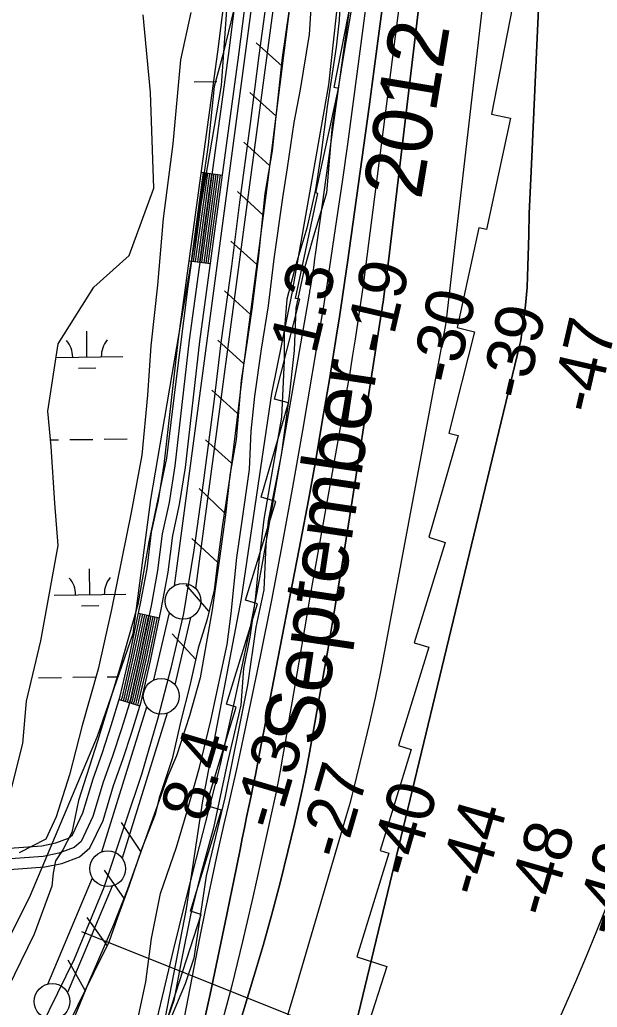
# Model space of a CAD drawing. Extents: x 3715084 to 3753216, y 488173 to 513963.
# Drawn here: x 3732143 to 3732951, y 502700 to 504083 of the extents above; entities that cross this region are included whole.
import ezdxf

# ---------------------------------------------------------------- set-up
doc = ezdxf.new("R2010")
doc.units = 0
for name, color, linetype in [('V-FLOD-BASE', 7, 'Continuous'), ('V-LEVE-TOET', 7, 'Continuous'), ('V-RIVR-EDGE', 7, 'Continuous'), ('V-RIVR-IDEN', 7, 'Continuous'), ('V-RIVR-RANG', 7, 'Continuous'), ('V-ROAD-CNTR', 7, 'Continuous'), ('V-RRAP-FSHR', 7, 'Continuous'), ('V-RRAP-RVMT', 7, 'Continuous'), ('V-SITE-VEGE', 7, 'Continuous'), ('V-SURV-LINE', 7, 'Continuous'), ('V-TOPO-DPTH', 7, 'Continuous'), ('V-TOPO-MAJR', 7, 'Continuous'), ('V-TOPO-MINR', 7, 'Continuous'), ('V-TOPO-WATR', 7, 'Continuous'), ('V-WETL-SWMP', 7, 'Continuous')]:
    doc.layers.add(name, color=color, linetype=linetype)

msp = doc.modelspace()

# ---------------------------------------------------------------- linework, layer by layer
at = {"layer": 'V-FLOD-BASE'}
msp.add_lwpolyline([(3732486.7, 504101), (3732477.1, 504032.8), (3732465.1, 503937.3), (3732449.9, 503823.6), (3732439.1, 503737.6), (3732424.5, 503634), (3732413.8, 503544.2), (3732399.2, 503434.3), (3732386.5, 503340.1), (3732371.9, 503251.6), (3732354.2, 503175.1), (3732335.9, 503105), (3732313.1, 503026), (3732290.9, 502959.6), (3732260.6, 502868), (3732218.8, 502767.5), (3732148.6, 502624.1)], dxfattribs=at)
at = {"layer": 'V-LEVE-TOET'}
for points in [[(3732456.3, 504155.4), (3732427.2, 504035.3), (3732414.6, 503989.2), (3732406.3, 503907.6), (3732391.1, 503800.8), (3732377.8, 503709.2), (3732360, 503568.9), (3732348, 503469), (3732323.3, 503352.1), (3732308.1, 503264.3), (3732282.8, 503175.2), (3732251.8, 503072.8), (3732225.2, 502990), (3732215.7, 502945.1), (3732203.1, 502920.5), (3732192.9, 502905.3), (3732189.8, 502888.2), (3732187.9, 502869.9), (3732163.2, 502802.9), (3732117, 502708.1), (3732083.5, 502637.4)], [(3732519.2, 504094.3), (3732509.7, 504029.8), (3732503.4, 503969.1), (3732495.7, 503899), (3732485.6, 503839.6), (3732476.7, 503752.4), (3732467.9, 503681), (3732460.9, 503632.9), (3732452.7, 503577.9), (3732445.7, 503495.1), (3732436.8, 503445.2), (3732430.5, 503389.6), (3732421.6, 503325.1), (3732412.1, 503256.9), (3732395, 503161.4), (3732380.4, 503108.4), (3732362.1, 503052.1), (3732350.1, 503023.7), (3732322.2, 502945.3), (3732293.1, 502864.4), (3732274.1, 502815.8), (3732239.3, 502736.1), (3732207.7, 502658.4)]]:
    msp.add_lwpolyline(points, dxfattribs=at)
at = {"layer": 'V-RIVR-EDGE'}
msp.add_lwpolyline([(3732610.8, 504121.1), (3732594.9, 504027.5), (3732579.7, 503934.5), (3732571.7, 503840.3), (3732552.9, 503776.7), (3732540.8, 503733.5), (3732529.2, 503678.9), (3732526.7, 503619.5), (3732519.9, 503556.4), (3732508.3, 503473), (3732490.1, 503381.2), (3732487, 503347.6), (3732484.4, 503284.6), (3732472.9, 503232.4), (3732461.3, 503151.4), (3732449.2, 503090.8), (3732429.7, 502993.6), (3732403.6, 502884.4), (3732386.5, 502769.1), (3732374.4, 502733.2), (3732353.9, 502684)], dxfattribs=at)
at = {"layer": 'V-RIVR-RANG'}
msp.add_line((3732229.3, 502806.2), (3732823.6, 502568.7), dxfattribs=at)
at = {"layer": 'V-ROAD-CNTR'}
for p, q in [((3732396.8, 503869.2), (3732426.5, 503865.1)), ((3732379.9, 503745.3), (3732409.6, 503741.3)), ((3732308.9, 503251.8), (3732338.3, 503245.6)), ((3732282.1, 503131.1), (3732310.7, 503122.3))]:
    msp.add_line(p, q, dxfattribs=at)
for points in [[(3731140.1, 502909.1), (3731460.2, 502909.4), (3731837.7, 502913.8), (3732083.1, 502919.7), (3732173.7, 502926.4), (3732193.3, 502930.5), (3732211.1, 502937.1), (3732216.7, 502941.9), (3732231.2, 502972.7), (3732245.4, 503020.3), (3732258.6, 503056.9), (3732270.9, 503094.6), (3732283.5, 503135.8), (3732296.3, 503191.6), (3732311.8, 503265.4), (3732320.9, 503314.1), (3732327.1, 503365.6), (3732337, 503409.7), (3732344.9, 503460.2), (3732365, 503636.2), (3732419.7, 504037.6), (3732449.2, 504271.2)], [(3732464.1, 504269.6), (3732434.6, 504035.7), (3732379.9, 503634.4), (3732359.8, 503458.2), (3732351.7, 503406.9), (3732341.9, 503363.1), (3732335.7, 503311.8), (3732326.5, 503262.5), (3732310.9, 503188.4), (3732298, 503131.9), (3732285.2, 503090), (3732272.8, 503052), (3732259.7, 503015.6), (3732245.3, 502967.3), (3732228.9, 502932.6), (3732218.9, 502924), (3732197.4, 502916.1), (3732175.8, 502911.6), (3732083.8, 502904.7), (3731837.9, 502898.8), (3731460.3, 502894.4), (3731140.2, 502894.1)], [(3731140.2, 502879.1), (3731460.4, 502879.4), (3731838.2, 502883.8), (3732084.6, 502889.8), (3732177.9, 502896.7), (3732201.6, 502901.6), (3732226.6, 502910.8), (3732241.1, 502923.3), (3732259.3, 502961.9), (3732274, 503011), (3732287, 503047.2), (3732299.5, 503085.5), (3732312.5, 503128), (3732325.6, 503185.2), (3732341.2, 503259.5), (3732350.6, 503309.5), (3732356.8, 503360.6), (3732366.5, 503404.1), (3732374.6, 503456.1), (3732394.8, 503632.5), (3732449.5, 504033.7), (3732479, 504268)], [(3732382.9, 503744.9), (3732399.7, 503868.8)], [(3732385.8, 503744.5), (3732402.7, 503868.4)], [(3732388.8, 503744.1), (3732405.7, 503868)], [(3732391.8, 503743.7), (3732408.7, 503867.6)], [(3732394.7, 503743.3), (3732411.6, 503867.2)], [(3732397.7, 503742.9), (3732414.6, 503866.8)], [(3732400.7, 503742.5), (3732417.6, 503866.4)], [(3732403.7, 503742.1), (3732420.5, 503866)], [(3732406.6, 503741.7), (3732423.5, 503865.5)], [(3732284.9, 503130.2), (3732286.4, 503135), (3732299.2, 503191), (3732311.9, 503251.2)], [(3732287.8, 503129.4), (3732289.3, 503134.3), (3732302.1, 503190.3), (3732314.8, 503250.6)], [(3732290.7, 503128.5), (3732292.2, 503133.5), (3732305.1, 503189.7), (3732317.7, 503249.9)], [(3732293.5, 503127.6), (3732295.1, 503132.7), (3732308, 503189), (3732320.7, 503249.3)], [(3732296.4, 503126.7), (3732298, 503131.9), (3732310.9, 503188.4), (3732323.6, 503248.7)], [(3732299.3, 503125.8), (3732300.9, 503131.2), (3732313.9, 503187.7), (3732326.5, 503248.1)], [(3732302.1, 503125), (3732303.8, 503130.4), (3732316.8, 503187.1), (3732329.5, 503247.5)], [(3732305, 503124.1), (3732306.7, 503129.6), (3732319.7, 503186.5), (3732332.4, 503246.9)], [(3732307.9, 503123.2), (3732309.6, 503128.8), (3732322.7, 503185.8), (3732335.4, 503246.2)]]:
    msp.add_lwpolyline(points, dxfattribs=at)
at = {"layer": 'V-RRAP-FSHR'}
for p, q in [((3732509.9, 504017.6), (3732473.7, 504050.4)), ((3732501.1, 503948.2), (3732464.9, 503981)), ((3732492.3, 503878.7), (3732456.1, 503911.5)), ((3732483.3, 503809.3), (3732447.3, 503842.2)), ((3732474.3, 503739.9), (3732438.2, 503772.8)), ((3732465.2, 503670.5), (3732429.2, 503703.4)), ((3732456.2, 503601.1), (3732420.1, 503634)), ((3732447.6, 503531.6), (3732411.3, 503564.3)), ((3732439, 503462.1), (3732402.7, 503494.8)), ((3732428.9, 503392.9), (3732393.6, 503426.6)), ((3732419.3, 503323.5), (3732383.4, 503356.6)), ((3732407.5, 503254.7), (3732375.5, 503291.5)), ((3732389, 503187.2), (3732356.1, 503223.3)), ((3732312.2, 502918.4), (3732285.1, 502959)), ((3732289.3, 502852.3), (3732261.5, 502892.4)), ((3732265.8, 502786.3), (3732237.2, 502825.9)), ((3732234.2, 502723.9), (3732210.4, 502766.5))]:
    msp.add_line(p, q, dxfattribs=at)
for points in [[(3732657, 504737.7), (3732623.4, 504423.9), (3732606.3, 504281.7), (3732574.5, 503991.8), (3732523.5, 503699.8), (3732494.9, 503559.3), (3732452.7, 503272.7), (3732398.5, 502989.1), (3732375.8, 502838.2), (3732346.1, 502686.7), (3732360.7, 502650.7)], [(3732534.3, 504210.7), (3732488.4, 503847.8), (3732455.4, 503595.5), (3732437, 503446.3), (3732426.3, 503376.2), (3732419.7, 503326.5), (3732414.9, 503284.3), (3732404.8, 503243.6), (3732392.5, 503203), (3732380.8, 503150.6), (3732368.2, 503101.4), (3732355.9, 503048.3), (3732337.8, 502993.6), (3732332.3, 502970.2), (3732313.8, 502922.5), (3732295.5, 502869.2), (3732279.5, 502825.9), (3732267.5, 502791.3), (3732245.8, 502747.9), (3732223.7, 502702.3), (3732204.2, 502662.3)], [(3732531.1, 504185), (3732488.4, 503847.8), (3732455.4, 503595.5), (3732437, 503446.3), (3732426.3, 503376.2), (3732419.7, 503326.5), (3732414.9, 503284.3), (3732404.8, 503243.6), (3732392.5, 503203), (3732382.2, 503156.7)], [(3732327.8, 502958.4), (3732313.8, 502922.5), (3732295.5, 502869.2), (3732279.5, 502825.9), (3732267.5, 502791.3), (3732245.8, 502747.9), (3732223.7, 502702.3), (3732223.6, 502702)]]:
    msp.add_lwpolyline(points, dxfattribs=at)
at = {"layer": 'V-RRAP-RVMT'}
for p, q in [((3732582.5, 503987.7), (3732609.8, 504126.9)), ((3732832.3, 504101.1), (3732802.6, 503950.7)), ((3732557.1, 503840.2), (3732588.5, 503986.5)), ((3732588.5, 503986.5), (3732582.5, 503987.7)), ((3732829.4, 503945), (3732795.9, 503789)), ((3732802.6, 503950.7), (3732829.4, 503945)), ((3732528.5, 503692.7), (3732560, 503839.6)), ((3732560, 503839.6), (3732557.1, 503840.2)), ((3732784.9, 503791.3), (3732754.8, 503651.9)), ((3732795.9, 503789), (3732784.9, 503791.3)), ((3732499.2, 503551.6), (3732534.4, 503691.4)), ((3732534.4, 503691.4), (3732528.5, 503692.7)), ((3732778.8, 503645.8), (3732743.2, 503504.2)), ((3732754.8, 503651.9), (3732778.8, 503645.8)), ((3732480.7, 503414.4), (3732518.9, 503546.6)), ((3732518.9, 503546.6), (3732499.2, 503551.6)), ((3732743.2, 503504.2), (3732756, 503500.6)), ((3732756, 503500.6), (3732714.9, 503358.2)), ((3732458.5, 503270.1), (3732501, 503408.5)), ((3732501, 503408.5), (3732480.7, 503414.4)), ((3732737.7, 503351), (3732694.5, 503210.7)), ((3732714.9, 503358.2), (3732737.7, 503351)), ((3732475.3, 503264.9), (3732458.5, 503270.1)), ((3732432.2, 503124.8), (3732475.3, 503264.9)), ((3732715, 503204.3), (3732672.7, 503066.6)), ((3732694.5, 503210.7), (3732715, 503204.3)), ((3732403.4, 502983), (3732445.7, 503120.6)), ((3732445.7, 503120.6), (3732432.2, 503124.8)), ((3732690.4, 503061.2), (3732646.9, 502919.8)), ((3732672.7, 503066.6), (3732690.4, 503061.2)), ((3732425.2, 502976.1), (3732403.4, 502983)), ((3732381.7, 502834.8), (3732425.2, 502976.1)), ((3732659.1, 502916), (3732614.4, 502771.1)), ((3732646.9, 502919.8), (3732659.1, 502916)), ((3732350.9, 502689), (3732396.6, 502830.3)), ((3732396.6, 502830.3), (3732381.7, 502834.8)), ((3732614.4, 502771.1), (3732656.4, 502757.6)), ((3732656.4, 502757.6), (3732607.4, 502606.1))]:
    msp.add_line(p, q, dxfattribs=at)
at = {"layer": 'V-SITE-VEGE'}
for points in [[(3732308.9, 502687.9), (3732319, 502736), (3732327.2, 502796.6), (3732339.9, 502859.8), (3732362, 502924.3), (3732377.2, 502974.9), (3732394.3, 503036.2), (3732410.1, 503101.9), (3732432.9, 503208.1), (3732438.6, 503251.7), (3732446.3, 503330.1), (3732454.5, 503384.4), (3732464, 503453.3), (3732466.5, 503507), (3732471.6, 503555.7), (3732481.1, 503621.4), (3732490.6, 503682.1), (3732498.9, 503747.9), (3732510.9, 503833.2), (3732517.2, 503875.5), (3732526.7, 503938.7), (3732535.6, 503984.9), (3732548.3, 504062), (3732552.1, 504129)], [(3732591.9, 504130.9), (3732589.4, 504082.2), (3732585.6, 504044.3), (3732572.9, 503961.5), (3732564, 503893.2), (3732556.4, 503845.2), (3732544.4, 503790.8), (3732529.2, 503739.6), (3732516.5, 503691.6), (3732512.7, 503644.8), (3732512.7, 503605.6), (3732508.9, 503526.6), (3732484.2, 503383.8), (3732477.2, 503323.7), (3732472.1, 503271.3), (3732464.5, 503218.2), (3732455.7, 503174.6), (3732451.9, 503123.4), (3732432.9, 503041.8), (3732413.9, 502951.5), (3732395.5, 502885.1), (3732382.2, 502831.4), (3732368.9, 502766.9), (3732358.2, 502710), (3732342.3, 502663.9)], [(3732382.2, 504092.8), (3732367.6, 504026.4), (3732356.8, 503908.9), (3732343.5, 503804.6), (3732335.3, 503711), (3732326.4, 503626.3), (3732321.3, 503557.4), (3732313.7, 503473.4), (3732298.5, 503393.1), (3732285.8, 503328.6), (3732271.3, 503257.2), (3732252.3, 503173.8), (3732230.1, 503094.8), (3732212.4, 503025.9), (3732194, 502967.1), (3732179.5, 502935.5), (3732142.2, 502916.6)]]:
    msp.add_lwpolyline(points, dxfattribs=at)
at = {"layer": 'V-SURV-LINE'}
for points in [[(3732359.1, 503290.5), (3732526.7, 504546.7)], [(3732556.5, 504542.7), (3732388.8, 503286.5)], [(3732330.5, 503158.6), (3732352.2, 503252.6)], [(3732381.5, 503245.9), (3732359.8, 503151.9)], [(3732257.5, 502917.8), (3732320.4, 503121.1)], [(3732349.1, 503112.2), (3732286.2, 502908.9)], [(3732182, 502732.8), (3732244.4, 502881.6)], [(3732272, 502870), (3732209.7, 502721.2)]]:
    msp.add_lwpolyline(points, dxfattribs=at)
for centre in [(3732371.3, 503268.7), (3732340.7, 503135.7), (3732265.9, 502894.3), (3732188.1, 502708.6)]:
    msp.add_circle(centre, 25, dxfattribs=at)
at = {"layer": 'V-TOPO-DPTH'}
for points in [[(3732626.4, 504261.1), (3732556.6, 503757.3), (3732555.3, 503748.2), (3732554, 503739.1), (3732552.6, 503730), (3732551.2, 503720.9), (3732548.9, 503706.9), (3732548.6, 503704.9), (3732548.3, 503702.8), (3732547.9, 503700.7), (3732547.5, 503698.6), (3732483.1, 503329.6), (3732474.3, 503281.1), (3732465, 503232.7), (3732455.1, 503184.5), (3732444.7, 503136.3), (3732429.9, 503069.7), (3732426.5, 503054.9), (3732423, 503040.2), (3732419.4, 503025.4), (3732415.7, 503010.7), (3732389.6, 502909.2), (3732373.3, 502844.8), (3732357.3, 502780.2), (3732341.9, 502715.5), (3732326.7, 502650.8)], [(3732719.2, 504255), (3732662, 503772.2), (3732660.1, 503756.6), (3732658.2, 503741.1), (3732656.2, 503725.6), (3732654.1, 503710.1), (3732651, 503687.5), (3732650.4, 503683.3), (3732649.8, 503679.1), (3732649.1, 503674.9), (3732648.5, 503670.7), (3732605.5, 503394.3), (3732595.2, 503329.5), (3732584.6, 503264.8), (3732573.6, 503200.1), (3732562.2, 503135.5), (3732548, 503056.4), (3732543.3, 503031.4), (3732538.3, 503006.5), (3732532.9, 502981.6), (3732527.1, 502956.8), (3732517.9, 502918.3), (3732506.9, 502874.4), (3732495.4, 502830.6), (3732483.2, 502787), (3732470.5, 502743.6), (3732406.1, 502530.1)], [(3732406.1, 502530.1), (3732470.5, 502743.6), (3732483.2, 502787), (3732495.4, 502830.6), (3732506.9, 502874.4), (3732517.9, 502918.3), (3732527.1, 502956.8), (3732532.9, 502981.6), (3732538.3, 503006.5), (3732543.3, 503031.4), (3732548, 503056.4), (3732562.2, 503135.5), (3732573.6, 503200.1), (3732584.6, 503264.8), (3732595.2, 503329.5), (3732605.5, 503394.3), (3732648.5, 503670.7), (3732649.1, 503674.9), (3732649.8, 503679.1), (3732650.4, 503683.3), (3732651, 503687.5), (3732654.1, 503710.1), (3732656.2, 503725.6), (3732658.2, 503741.1), (3732660.1, 503756.6), (3732662, 503772.2), (3732719.2, 504255)], [(3732807.4, 504254.4), (3732738.9, 503658.3), (3732654.6, 503206.9), (3732647.4, 503170), (3732639.8, 503133.3), (3732631.6, 503096.6), (3732622.9, 503060), (3732609.8, 503006.2), (3732607.4, 502996.6), (3732604.9, 502987.1), (3732602.2, 502977.6), (3732599.5, 502968.1), (3732527.6, 502723.5), (3732514, 502678.3)], [(3732807.4, 504254.4), (3732738.9, 503658.3), (3732654.6, 503206.9), (3732647.4, 503170), (3732639.8, 503133.3), (3732631.6, 503096.6), (3732622.9, 503060), (3732609.8, 503006.2), (3732607.4, 502996.6), (3732604.9, 502987.1), (3732602.2, 502977.6), (3732599.5, 502968.1), (3732527.6, 502723.5), (3732514, 502678.3)], [(3732401, 502681.1), (3732409.3, 502718.5), (3732432.5, 502830.2), (3732437.2, 502852.9), (3732441.8, 502875.6), (3732446.4, 502898.3), (3732451, 502921), (3732454.1, 502936.7), (3732457.1, 502951.6), (3732460.1, 502966.4), (3732463.2, 502981.2), (3732466.4, 502996.1), (3732469.5, 503010.9), (3732472.5, 503025.7), (3732475.5, 503040.6), (3732478.4, 503055.4), (3732536, 503354.2), (3732546.6, 503410.4), (3732556.8, 503466.6), (3732566.5, 503522.9), (3732575.9, 503579.2), (3732586, 503641.2), (3732590.1, 503666.7), (3732594, 503692.1), (3732597.7, 503717.5), (3732601.3, 503743), (3732631.5, 503961), (3732638.7, 504013.9), (3732645.8, 504066.9), (3732652.8, 504119.9)], [(3732401, 502681.1), (3732409.3, 502718.5), (3732432.5, 502830.2), (3732437.2, 502852.9), (3732441.8, 502875.6), (3732446.4, 502898.3), (3732451, 502921), (3732454.1, 502936.7), (3732457.1, 502951.6), (3732460.1, 502966.4), (3732463.2, 502981.2), (3732466.4, 502996.1), (3732469.5, 503010.9), (3732472.5, 503025.7), (3732475.5, 503040.6), (3732478.4, 503055.4), (3732536, 503354.2), (3732546.6, 503410.4), (3732556.8, 503466.6), (3732566.5, 503522.9), (3732575.9, 503579.2), (3732586, 503641.2), (3732590.1, 503666.7), (3732594, 503692.1), (3732597.7, 503717.5), (3732601.3, 503743), (3732631.5, 503961), (3732638.7, 504013.9), (3732645.8, 504066.9), (3732652.8, 504119.9)], [(3732616, 502689.8), (3732682.2, 502964.6), (3732842, 503626.4), (3732842.8, 503630.1), (3732843.6, 503633.8), (3732844.2, 503637.6), (3732844.8, 503641.4), (3732848, 503663.5), (3732849.9, 503678.3), (3732851.4, 503693.2), (3732852.4, 503708.2), (3732853.1, 503723.1), (3732853.8, 503752.3), (3732854.7, 503781.8), (3732855.6, 503811.4), (3732856.7, 503840.9), (3732858, 503870.4), (3732866.9, 504067.5), (3732868.3, 504097.8)], [(3732616, 502689.8), (3732682.2, 502964.6), (3732842, 503626.4), (3732842.8, 503630.1), (3732843.6, 503633.8), (3732844.2, 503637.6), (3732844.8, 503641.4), (3732848, 503663.5), (3732849.9, 503678.3), (3732851.4, 503693.2), (3732852.4, 503708.2), (3732853.1, 503723.1), (3732853.8, 503752.3), (3732854.7, 503781.8), (3732855.6, 503811.4), (3732856.7, 503840.9), (3732858, 503870.4), (3732866.9, 504067.5), (3732868.3, 504097.8)]]:
    msp.add_lwpolyline(points, dxfattribs=at)
at = {"layer": 'V-TOPO-MAJR'}
msp.add_lwpolyline([(3732975.1, 502870.4), (3732949.7, 502806.9), (3732935.2, 502771.4), (3732920.4, 502736), (3732905, 502700.9), (3732889.4, 502665.8)], dxfattribs=at)
at = {"layer": 'V-TOPO-MINR'}
for points in [[(3732719.2, 504255), (3732662, 503772.2), (3732660.1, 503756.6), (3732658.2, 503741.1), (3732656.2, 503725.6), (3732654.1, 503710.1), (3732651, 503687.5), (3732650.4, 503683.3), (3732649.8, 503679.1), (3732649.1, 503674.9), (3732648.5, 503670.7), (3732605.5, 503394.3), (3732595.2, 503329.5), (3732584.6, 503264.8), (3732573.6, 503200.1), (3732562.2, 503135.5), (3732548, 503056.4), (3732543.3, 503031.4), (3732538.3, 503006.5), (3732532.9, 502981.6), (3732527.1, 502956.8), (3732517.9, 502918.3), (3732506.9, 502874.4), (3732495.4, 502830.6), (3732483.2, 502787), (3732470.5, 502743.6), (3732406.1, 502530.1)], [(3732807.4, 504254.4), (3732738.9, 503658.3), (3732654.6, 503206.9), (3732647.4, 503170), (3732639.8, 503133.3), (3732631.6, 503096.6), (3732622.9, 503060), (3732609.8, 503006.2), (3732607.4, 502996.6), (3732604.9, 502987.1), (3732602.2, 502977.6), (3732599.5, 502968.1), (3732527.6, 502723.5), (3732514, 502678.3)], [(3732644.7, 504237), (3732615.5, 504013.9), (3732608.4, 503961.1), (3732601.1, 503908.4), (3732593.6, 503855.7), (3732585.9, 503803), (3732574.2, 503724.1), (3732572.2, 503710.9), (3732570.1, 503697.7), (3732568, 503684.5), (3732565.8, 503671.2), (3732538.3, 503507.8), (3732524.5, 503428.4), (3732510.1, 503349.2), (3732494.8, 503270.1), (3732478.9, 503191.2), (3732457.2, 503086.5), (3732451.6, 503060), (3732445.9, 503033.5), (3732440, 503007), (3732434, 502980.6), (3732428, 502954.8), (3732419.1, 502915.4), (3732410.5, 502876), (3732402.3, 502836.5), (3732394.4, 502796.9), (3732372.9, 502685.9)], [(3732684.4, 504187.1), (3732626.5, 503736.6), (3732623.1, 503711.3), (3732619.6, 503686.1), (3732615.9, 503660.9), (3732612.1, 503635.7), (3732608, 503610.5), (3732603.9, 503585.4), (3732599.6, 503560.3), (3732595.2, 503535.2), (3732565.7, 503370.6), (3732557.4, 503323.8), (3732549.2, 503277.1), (3732541.1, 503230.3), (3732533.1, 503183.5), (3732523.4, 503126.6), (3732520.3, 503108.2), (3732517.2, 503089.9), (3732514, 503071.5), (3732510.8, 503053.1), (3732507, 503031.1), (3732505.7, 503023.7), (3732504.3, 503016.4), (3732502.8, 503009.2), (3732501.3, 503001.9), (3732468.9, 502854.4), (3732454.6, 502792.6), (3732439.5, 502731), (3732423.1, 502669.8)], [(3732652.8, 504119.9), (3732645.8, 504066.9), (3732638.7, 504013.9), (3732631.5, 503961), (3732601.3, 503743), (3732597.7, 503717.5), (3732594, 503692.1), (3732590.1, 503666.7), (3732586, 503641.2), (3732575.9, 503579.2), (3732566.5, 503522.9), (3732556.8, 503466.6), (3732546.6, 503410.4), (3732536, 503354.2), (3732478.4, 503055.4), (3732475.5, 503040.6), (3732472.5, 503025.7), (3732469.5, 503010.9), (3732466.4, 502996.1), (3732463.2, 502981.2), (3732460.1, 502966.4), (3732457.1, 502951.6), (3732454.1, 502936.7), (3732451, 502921), (3732446.4, 502898.3), (3732441.8, 502875.6), (3732437.2, 502852.9), (3732432.5, 502830.2), (3732409.3, 502718.5), (3732401, 502681.1)], [(3732868.3, 504097.8), (3732866.9, 504067.5), (3732858, 503870.4), (3732856.7, 503840.9), (3732855.6, 503811.4), (3732854.7, 503781.8), (3732853.8, 503752.3), (3732853.1, 503723.1), (3732852.4, 503708.2), (3732851.4, 503693.2), (3732849.9, 503678.3), (3732848, 503663.5), (3732844.8, 503641.4), (3732844.2, 503637.6), (3732843.6, 503633.8), (3732842.8, 503630.1), (3732842, 503626.4), (3732682.2, 502964.6), (3732616, 502689.8)]]:
    msp.add_lwpolyline(points, dxfattribs=at)
at = {"layer": 'V-TOPO-WATR'}
msp.add_lwpolyline([(3732626.4, 504261.1), (3732556.6, 503757.3), (3732555.3, 503748.2), (3732554, 503739.1), (3732552.6, 503730), (3732551.2, 503720.9), (3732548.9, 503706.9), (3732548.6, 503704.9), (3732548.3, 503702.8), (3732547.9, 503700.7), (3732547.5, 503698.6), (3732483.1, 503329.6), (3732474.3, 503281.1), (3732465, 503232.7), (3732455.1, 503184.5), (3732444.7, 503136.3), (3732429.9, 503069.7), (3732426.5, 503054.9), (3732423, 503040.2), (3732419.4, 503025.4), (3732415.7, 503010.7), (3732389.6, 502909.2), (3732373.3, 502844.8), (3732357.3, 502780.2), (3732341.9, 502715.5), (3732326.7, 502650.8)], dxfattribs=at)
at = {"layer": 'V-WETL-SWMP'}
for p, q in [((3732386.7, 503996), (3732418.7, 503996.4)), ((3732236.9, 503610.7), (3732236.5, 503646.7)), ((3732193.8, 503610.1), (3732286.9, 503611.3)), ((3732225.1, 503595.1), (3732249.1, 503595.4)), ((3732186, 503494.6), (3732196.9, 503494.7)), ((3732212.9, 503494.9), (3732244.9, 503495.3)), ((3732260.9, 503495.5), (3732292.9, 503495.9)), ((3732241.1, 503278), (3732240.6, 503314)), ((3732191.1, 503277.4), (3732291.1, 503278.6)), ((3732229.3, 503262.4), (3732253.3, 503262.7)), ((3732169.1, 503161.7), (3732201.1, 503162.1)), ((3732217.1, 503162.3), (3732249.1, 503162.7)), ((3732265.1, 503162.9), (3732280.1, 503163.1))]:
    msp.add_line(p, q, dxfattribs=at)
for points in [[(3732459.3, 504480.8), (3732424.6, 503990.6), (3732325.6, 503411.2), (3732300.8, 503223), (3732251.3, 503079.4), (3732157.2, 502856.6), (3732073, 502688.2), (3732038.4, 502584.2), (3731914.6, 502376.3), (3731716.5, 502133.6), (3731459, 501930.6), (3731201.5, 501747.4), (3730904.4, 501608.7), (3730661.7, 501489.9), (3730305.2, 501415.6), (3729938.8, 501395.8)], [(3731860.1, 502673.4), (3731924.5, 502708), (3731978.9, 502737.7), (3732068.1, 502817), (3732107.7, 502940.8), (3732132.4, 503010.1), (3732147.3, 503069.5), (3732152.3, 503128.9), (3732172.1, 503213.1), (3732196.8, 503346.8), (3732191.9, 503406.2), (3732186.9, 503485.5), (3732182, 503535), (3732196.8, 503629.1), (3732246.3, 503708.3), (3732295.9, 503752.9), (3732330.5, 503847), (3732325.6, 503980.7), (3732315.7, 504089.6)]]:
    msp.add_lwpolyline(points, dxfattribs=at)
for centre, start, end in [((3732181.7, 503610.5), 359.9442, 41.4878), ((3732292.1, 503611.8), 139.9442, 181.4878), ((3732185.8, 503277.8), 359.9442, 41.4878), ((3732296.3, 503279.2), 139.9442, 181.4878)]:
    msp.add_arc(centre, 35.2, start, end, dxfattribs=at)

# ---------------------------------------------------------------- texts
at = {"layer": 'V-RIVR-IDEN'}
for s, rotation, p in [('2012', 80.5702, (3732704.2, 503829.6)), ('September', 81.5207, (3732563.8, 503063.6))]:
    msp.add_text(s, height=83, rotation=rotation, dxfattribs=at).set_placement(p)
at = {"layer": 'V-RIVR-RANG'}
for s, rotation, p in [('1.3', 76.7183, (3732557.1, 503612.9)), ('-19', 77.0066, (3732659.7, 503610.8)), ('-30', 77.0066, (3732753, 503570)), ('-39', 77.0066, (3732850.6, 503548.3)), ('-47', 77.0066, (3732948.7, 503529)), ('8.4', 73.5883, (3732402.2, 502957.1)), ('-13', 73.5883, (3732503.1, 502946.1)), ('-27', 73.8749, (3732595.7, 502905)), ('-40', 73.8749, (3732692.4, 502879.2)), ('-44', 73.8749, (3732788.7, 502852.2)), ('-48', 73.8749, (3732884.4, 502823.5)), ('-49', 73.8749, (3732980.6, 502796.2))]:
    msp.add_text(s, height=67, rotation=rotation, dxfattribs=at).set_placement(p)

doc.saveas('drawing.dxf')
